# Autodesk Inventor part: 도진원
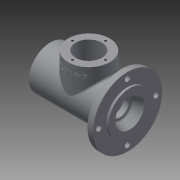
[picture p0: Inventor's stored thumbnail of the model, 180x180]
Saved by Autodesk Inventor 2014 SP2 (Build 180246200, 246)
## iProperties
Created: 2016-08
Part Number: 도진원
Material: Generic
Document SubType Name: Modeling
Designer: 달님반
Density: 1 g/cm^3
Appearance: Default
Mass: 290.959 g
Surface Area: 603.973 cm^2
Volume: 290.959 cm^3
Author: 달님반
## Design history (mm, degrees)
sketch "스케치1"
  geometry: L1 (0, 0)-(115, 0); L2 (0, 21)-(0, 31); L3 (0, 31)-(102, 31); L4 (102, 31)-(102, 50); L5 (102, 50)-(112, 50); L6 (112, 50)-(112, 31); L7 (112, 31)-(115, 31); L8 (115, 31)-(115, 21); L9 (115, 21)-(102.991, 16.711); L10 (87.3, 16.5)-(86, 16.5); L11 (86, 16.5)-(86, 17.2); L12 (85.7, 17.5)-(26, 17.5); L13 (26, 17.5)-(26, 18.5); L14 (26, 18.5)-(24.25, 18.5); L15 (24.25, 18.5)-(24.25, 17.5); L16 (24.25, 17.5)-(21, 17.5); L17 (21, 17.5)-(21, 20); L18 (21, 20)-(12, 20); L19 (12, 20)-(12, 24); L20 (12, 24)-(9, 24); L21 (9, 24)-(9, 21); L22 (9, 21)-(0, 21); L23 (101, 13.886)-(101, 12.75); L24 (90.3, 13.5)-(90.3, 10); L25 (90.3, 10)-(93, 10); L26 (93, 10)-(93, 12.2); L27 (93.3, 12.5)-(100.3, 12.5); L28 (101, 12.75)-(100.3, 12.5); A1 r 0.3 centre (93.3, 12.2) between (93.3, 12.5) and (93, 12.2); A2 r 0.3 centre (85.7, 17.2) between (86, 17.2) and (85.7, 17.5); A3 r 3 centre (87.3, 13.5) between (90.3, 13.5) and (87.3, 16.5); A4 r 3 centre (104, 13.886) between (102.991, 16.711) and (101, 13.886); 4 further points
  constraints: 56 end point, 15 parallel, 8 perpendicular, 8 point on circle, 8 point on line, 8 tangent, 4 centre point, 2 collinear, 2 vertical alignment, 1 horizontal
  dimensions: "d19" = 3 distance of L19.end L20.end; "d20" = 21 distance between parallel lines of L17 L2; "d21" = 1.75 distance of L13.end L14.end; "d23" = 26 distance between parallel lines of L13 L2; "d26" = 3 distance of L6.end L7.end; "d27" = 13 distance between parallel lines of L8 L4; "d28" = 14 distance from line of point (101, 16) L8; "d30" = 115 distance between parallel lines of L8 L2; "d31" = 35 diameter of L12 L1; "d32" = 37 diameter of L14 L1; "d33" = 35 diameter of L16 L1; "d34" = 40 diameter of L18 L1; "d35" = 48 diameter of L20 L1; "d36" = 42 diameter of L22 L1; "d37" = 62 diameter of L3 L1; "d38" = 33 diameter of L10 L1; "d40" = 20 diameter of L25 L1; "d41" = 25 diameter of L27 L1; "d42" = 2.7 distance of L24.end L25.end; "d43" = 7.3 distance of point (93, 12.5) L27.end; "d45" = 60 distance of point (86, 17.5) L12.end; "d46" = 0.7 horizontal distance of L23.end L27.end; "d47" = 0.3 radius of A1; "d48" = 32 diameter of point (101, 16) L1; "d49" = 42 diameter of L8.end L1; "d50" = 62 diameter of L7 L1; "d51" = 100 diameter of L5 L1; "d53" = 0.3 radius of A2; "d54" = 3 radius of A3; "d90" = 12 distance between parallel lines of L19 L2; "d91" = 3 radius of A4
revolve "회전1" sketch "스케치1" stored, may be unused: angle "d52" = 90 deg
node "작업 평면1"
sketch "스케치2"
  geometry: L1 (0, -31)-(0, 31) reference; C1 r 30 at (56, 0); 1 further point
  constraints: 1 centre point
  dimensions: "d56" = 60 diameter of C1; "d57" = 56 distance from line of C1.centre L1
extrude "돌출1" join sketch "스케치2" stored distance "d58" = 10; taper "d59" = 0 deg
sketch "스케치3"
  geometry: C1 r 30 at (0, 0) reference; 1 further point
sketch "스케치4"
  geometry: L1 (0, -31)-(-102, -31) reference; L2 (-122.4, 49)-(20.4, 49) reference; L3 (-55.721, 49)-(-36.721, 49); L4 (-36.721, 49)-(-36.721, -23); L5 (-36.721, -23)-(-55.721, -23); L6 (-55.721, -23)-(-55.721, 49); 1 further point
  constraints: 8 end point, 2 parallel, 1 horizontal, 1 perpendicular, 1 point on line
  dimensions: "d62" = 38 diameter of L4 L6; "d89" = 8 distance between parallel lines of L1 L5
revolve "회전2" sketch "스케치4" stored, may be unused: angle "d63" = 90 deg
sketch "스케치5" dims "d64" = 48
  geometry: C1 r 30 at (0, 0) reference; 3 further points
  constraints: 1 coincident, 1 vertical alignment, 2 other
hole "구멍1" sketch "스케치5" at (0, 24) diameter "d65" = 3.242; stored, may be unused: countersink angle "d69" = 90 deg, drill point angle "d71" = 118 deg; dims "d66" = 8, "d67" = 4, "d68" = 2, "d70" = 10
sketch "스케치6" dims "d75" = 83
  geometry: C1 r 50 at (0, 0) reference; C2 r 4 at (-41.5, 0); 1 further point
  constraints: 1 centre point, 1 coincident, 1 horizontal alignment, 2 other
  dimensions: "d76" = 8 diameter of C2
extrude "돌출2" cut sketch "스케치6" distance "d77" = 10; taper "d78" = 0 deg
fillet "모깎기1" dims "d82" = 3
fillet "모깎기2" dims "d83" = 3
sketch "스케치7"
  geometry: 1 further point
node "작업 평면2"
sketch "스케치8"
  geometry: L1 (-75.714, 42.388)-(-36.828, 42.388); L2 (-36.828, 42.388)-(-36.828, 32.322); L3 (-36.828, 32.322)-(-75.714, 32.322); L4 (-75.714, 32.322)-(-75.714, 42.388); 2 further points
  constraints: 1 midpoint, 2 other
feature "엠보싱1" sketch "스케치8" dims "d85" = 0.5, "d86" = 0
feature "스레드1" dims "d87" = 10, "d88" = 0
node "솔리드1"
pattern_circular "원형 패턴1" dims angle "d73" = 360 deg
pattern_circular "원형 패턴2" dims angle "d80" = 360 deg
other parameters: "d55" = 49
